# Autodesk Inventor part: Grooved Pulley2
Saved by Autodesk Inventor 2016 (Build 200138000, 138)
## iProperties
Created: 2015-03
Part Number: Grooved Pulley2
Material: Steel
Document SubType Name: Modeling
Designer: Uglješa
Density: 1 g/cm^3
Appearance: Steel
CustomPartVersion: 1
Author: Uglješa
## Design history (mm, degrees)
sketch "Main Sketch"
  geometry: L1 (0, 76)-(42, 76); L2 (42, 76)-(42, 12.861); L3 (42, 12.861)-(31, 9.498); L4 (31, 9.498)-(31, 6.502); L5 (31, 6.502)-(42, 3.139); L6 (42, 3.139)-(42, 0); L7 (42, 0)-(0, 0); L8 (40, 12.25)-(40, 3.75); L9 (31, 8)-(40, 8); L10 (42, 12.861)-(42, 3.139); L11 (0, -4)-(0, 24) reference; L12 (0, 0)-(0, 76)
  constraints: 22 end point, 5 perpendicular, 2 collinear, 2 midpoint, 2 point on line, 1 parallel
  dimensions: "d0" = 8.5 distance of L8.start L8.end (= da_Bw); "d1" = 34 deg angle of L3 L5 (= da_Alfa); "d2" = 2 distance between parallel lines of L2 L8 (= da_c); "d6" = 76 distance between parallel lines of L7 L1 (computed from d5, da_ng, da_Sg); "d21" = 80 diameter of L8 L11 (= da_Dw); "d25" = 11 distance between parallel lines of L4 L10 (= da_Hd); "d27" = 8 distance between parallel lines of L7 L9 (= da_Se)
node "Belt Plane"
revolve "Body" stored, may be unused: angle "d7" = 90 deg
revolve "Groove" stored, may be unused: angle "d15" = 90 deg
fillet "Fillet External" dims "d8" = 0 (computed from da_r1), "d10" = 0, "da_r1" = 0 [user parameter; used in 1 equation term]
fillet "Fillet Internal" dims "d9" = 0 (computed from da_r2), "d11" = 0, "da_r2" = 0 [user parameter; used in 1 equation term]
pattern_linear "Groove Pattern" dims "d18" = 12 (= da_Sg)
node "Keyway1"
body "Solid1"
feature "Hub Keyway"
other parameters: "d5" = 8 (= da_Se), "da_Bw" = 8.5 [user parameter; used in 1 equation term], "da_Alfa" = 34 deg [user parameter; used in 1 equation term], "da_c" = 2 [user parameter; used in 1 equation term], "da_Dw" = 80 [user parameter; used in 1 equation term], "da_Hd" = 11 [user parameter; used in 1 equation term], "da_Se" = 8 [user parameter; used in 2 equation terms], "da_Sg" = 12 [user parameter; used in 2 equation terms], "d24" = 0, "d26" = 0
